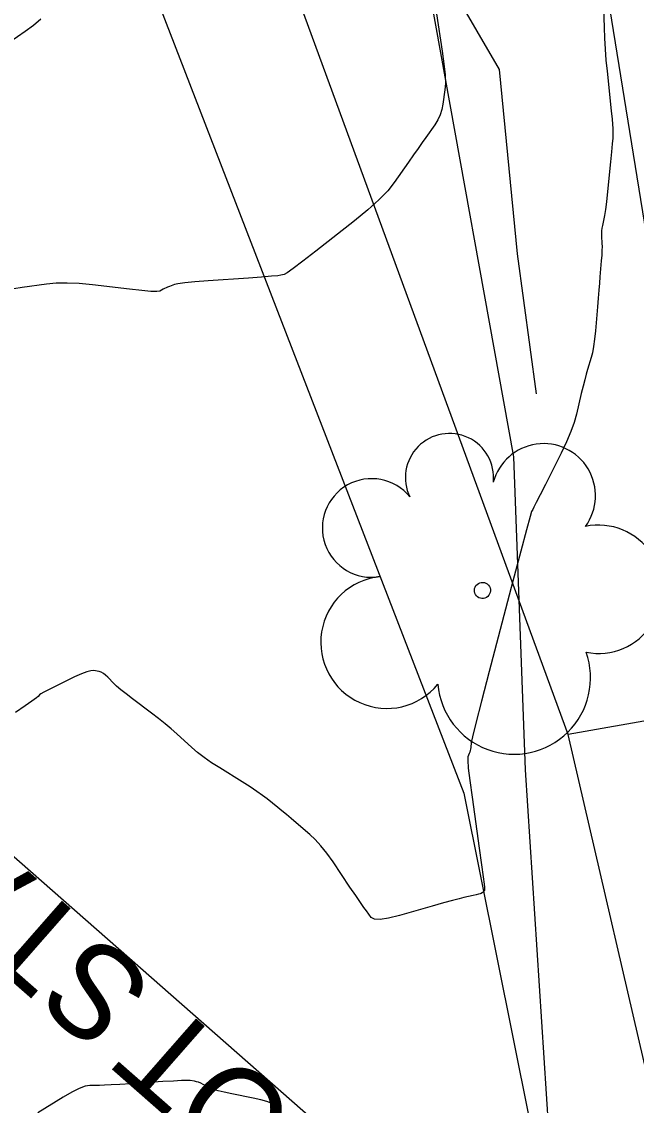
# Model space of a CAD drawing. Extents: x 2030588 to 2035216, y 462285 to 465007.
# Drawn here: x 2031209.6 to 2031227.95, y 464240.7 to 464273.04 of the extents above; entities that cross this region are included whole.
import ezdxf

# ---------------------------------------------------------------- set-up
doc = ezdxf.new("R2010")
doc.units = 0
for name, color, linetype in [('DT_P_Slope_Break_Line', 7, 'Continuous'), ('DT_X_Contour_Major', 7, 'Continuous'), ('DT_X_Contour_Minor', 7, 'Continuous'), ('GE_P_Alignment_100_Cardinal_Points', 7, 'Continuous'), ('MD_P_CONST_LIMITS', 7, 'Continuous'), ('RW_X_Esmt_SH', 7, 'Continuous'), ('SV_X_Toe_of_Slope', 7, 'Continuous'), ('VG_X_Cells', 7, 'Continuous'), ('VG_X_Tree_Line_Lt', 7, 'Continuous')]:
    doc.layers.add(name, color=color, linetype=linetype)

msp = doc.modelspace()

# ---------------------------------------------------------------- linework, layer by layer
at = {"layer": 'DT_P_Slope_Break_Line'}
for p, q in [((2031225.918, 464251.764), (2031216.941, 464276.229)), ((2031234.605, 464253.315), (2031225.918, 464251.764)), ((2031231.768, 464226.532), (2031225.918, 464251.764))]:
    msp.add_line(p, q, dxfattribs=at)
at = {"layer": 'DT_X_Contour_Major'}
msp.add_lwpolyline([(2031226.961, 464273.725), (2031226.988, 464272.871), (2031227.001, 464272.55), (2031227.021, 464272.225), (2031227.047, 464271.897), (2031227.08, 464271.565), (2031227.174, 464270.676), (2031227.206, 464270.375), (2031227.228, 464270.14), (2031227.243, 464269.969), (2031227.248, 464269.864), (2031227.251, 464269.669), (2031227.248, 464269.564), (2031227.236, 464269.394), (2031227.215, 464269.158), (2031227.184, 464268.857), (2031227.091, 464267.968), (2031227.059, 464267.667), (2031227.03, 464267.431), (2031227.006, 464267.259), (2031226.986, 464267.153), (2031226.939, 464266.954), (2031226.925, 464266.879), (2031226.915, 464266.802), (2031226.912, 464266.723), (2031226.914, 464266.642), (2031226.926, 464266.423), (2031226.928, 464266.329), (2031226.926, 464266.211), (2031226.918, 464266.069), (2031226.905, 464265.903), (2031226.865, 464265.428), (2031226.849, 464265.238), (2031226.832, 464265.026), (2031226.812, 464264.791), (2031226.79, 464264.533), (2031226.729, 464263.815), (2031226.705, 464263.563), (2031226.675, 464263.345), (2031226.642, 464263.162), (2031226.604, 464263.014), (2031226.498, 464262.664), (2031226.456, 464262.52), (2031226.411, 464262.352), (2031226.363, 464262.158), (2031226.31, 464261.94), (2031226.167, 464261.326), (2031226.097, 464261.081), (2031225.998, 464260.805), (2031225.867, 464260.5), (2031225.706, 464260.165), (2031225.237, 464259.232), (2031225.081, 464258.922), (2031224.966, 464258.694), (2031224.892, 464258.548), (2031224.858, 464258.483), (2031224.824, 464258.418), (2031224.779, 464258.27), (2031224.672, 464257.876), (2031224.502, 464257.234), (2031224.269, 464256.347), (2031223.563, 464253.65), (2031223.33, 464252.759), (2031223.163, 464252.107), (2031223.06, 464251.695), (2031223.022, 464251.523), (2031223.008, 464251.383), (2031223.001, 464251.333), (2031222.991, 464251.286), (2031222.979, 464251.243), (2031222.964, 464251.203), (2031222.921, 464251.103), (2031222.917, 464250.999), (2031222.936, 464250.763), (2031222.979, 464250.394), (2031223.046, 464249.893), (2031223.256, 464248.379), (2031223.325, 464247.88), (2031223.375, 464247.519), (2031223.406, 464247.296), (2031223.417, 464247.21), (2031223.422, 464247.166), (2031223.423, 464247.15), (2031223.422, 464247.136), (2031223.42, 464247.124), (2031223.416, 464247.114), (2031223.403, 464247.091), (2031223.397, 464247.082), (2031223.388, 464247.072), (2031223.376, 464247.063), (2031223.362, 464247.053), (2031223.318, 464247.025), (2031223.291, 464247.014), (2031223.242, 464246.999), (2031223.17, 464246.981), (2031223.077, 464246.959), (2031222.799, 464246.899), (2031222.662, 464246.866), (2031222.459, 464246.813), (2031222.191, 464246.739), (2031221.857, 464246.646), (2031220.88, 464246.369), (2031220.553, 464246.288), (2031220.303, 464246.25), (2031220.131, 464246.257), (2031220.038, 464246.308), (2031219.892, 464246.504), (2031219.82, 464246.603), (2031219.715, 464246.754), (2031219.575, 464246.957), (2031219.402, 464247.212), (2031218.895, 464247.962), (2031218.709, 464248.224), (2031218.533, 464248.448), (2031218.365, 464248.635), (2031218.206, 464248.784), (2031217.794, 464249.131), (2031217.644, 464249.257), (2031217.503, 464249.375), (2031217.371, 464249.485), (2031217.247, 464249.586), (2031216.928, 464249.846), (2031216.792, 464249.95), (2031216.623, 464250.07), (2031216.42, 464250.204), (2031216.184, 464250.353), (2031215.511, 464250.769), (2031215.269, 464250.925), (2031215.049, 464251.079), (2031214.851, 464251.231), (2031214.675, 464251.382), (2031214.234, 464251.782), (2031214.063, 464251.933), (2031213.88, 464252.087), (2031213.684, 464252.243), (2031213.477, 464252.402), (2031212.909, 464252.828), (2031212.714, 464252.977), (2031212.556, 464253.104), (2031212.434, 464253.208), (2031212.348, 464253.29), (2031212.169, 464253.479), (2031212.102, 464253.542), (2031212.036, 464253.591), (2031211.972, 464253.624), (2031211.909, 464253.643), (2031211.743, 464253.674), (2031211.661, 464253.671), (2031211.539, 464253.638), (2031211.379, 464253.576), (2031211.179, 464253.484), (2031210.594, 464253.2), (2031210.4, 464253.104), (2031210.258, 464253.031), (2031210.167, 464252.979), (2031210.127, 464252.95), (2031210.089, 464252.902), (2031210.036, 464252.859), (2031209.905, 464252.765), (2031209.697, 464252.62), (2031209.412, 464252.425)], dxfattribs=at)
at = {"layer": 'DT_X_Contour_Minor'}
for points in [[(2031210.168, 464273.117), (2031209.946, 464272.926), (2031209.701, 464272.744), (2031209.018, 464272.269)], [(2031221.984, 464273.272), (2031222.155, 464272.162), (2031222.209, 464271.778), (2031222.24, 464271.457), (2031222.25, 464271.2), (2031222.239, 464271.006), (2031222.179, 464270.575), (2031222.147, 464270.415), (2031222.095, 464270.261), (2031222.025, 464270.111), (2031221.935, 464269.966), (2031221.669, 464269.587), (2031221.562, 464269.434), (2031221.44, 464269.26), (2031221.303, 464269.064), (2031221.15, 464268.846), (2031220.724, 464268.237), (2031220.529, 464267.995), (2031220.266, 464267.724), (2031219.935, 464267.426), (2031219.536, 464267.1), (2031218.378, 464266.193), (2031217.994, 464265.895), (2031217.709, 464265.679), (2031217.523, 464265.546), (2031217.437, 464265.495), (2031217.339, 464265.471), (2031217.251, 464265.459), (2031217.059, 464265.441), (2031216.764, 464265.418), (2031216.367, 464265.389), (2031215.168, 464265.304), (2031214.768, 464265.274), (2031214.466, 464265.246), (2031214.263, 464265.221), (2031214.158, 464265.198), (2031214.01, 464265.141), (2031213.957, 464265.12), (2031213.908, 464265.098), (2031213.863, 464265.077), (2031213.823, 464265.055), (2031213.721, 464264.998), (2031213.636, 464264.986), (2031213.457, 464264.991), (2031213.183, 464265.014), (2031212.815, 464265.054), (2031211.709, 464265.186), (2031211.312, 464265.225), (2031210.951, 464265.241), (2031210.625, 464265.236), (2031210.335, 464265.209), (2031209.61, 464265.106), (2031209.359, 464265.065)], [(2031217.187, 464240.699), (2031217.073, 464240.755), (2031216.922, 464240.809), (2031216.735, 464240.861), (2031216.512, 464240.91), (2031215.869, 464241.039), (2031215.648, 464241.087), (2031215.468, 464241.132), (2031215.329, 464241.175), (2031215.23, 464241.216), (2031215.02, 464241.322), (2031214.945, 464241.358), (2031214.877, 464241.386), (2031214.816, 464241.405), (2031214.761, 464241.417), (2031214.626, 464241.437), (2031214.537, 464241.441), (2031214.371, 464241.437), (2031214.129, 464241.425), (2031213.811, 464241.406), (2031212.859, 464241.343), (2031212.533, 464241.322), (2031212.269, 464241.308), (2031212.066, 464241.298), (2031211.924, 464241.295), (2031211.628, 464241.293), (2031211.495, 464241.271), (2031211.319, 464241.205), (2031211.1, 464241.095), (2031210.838, 464240.942), (2031210.082, 464240.475)]]:
    msp.add_lwpolyline(points, dxfattribs=at)
at = {"layer": 'GE_P_Alignment_100_Cardinal_Points'}
msp.add_line((2031185.644, 464268.94), (2031219.463, 464239.26), dxfattribs=at)
at = {"layer": 'MD_P_CONST_LIMITS'}
msp.add_lwpolyline([(2031213.423, 464452.904), (2031204.569, 464426.156), (2031208.548, 464401.477), (2031212.527, 464376.798), (2031213.545, 464351.642), (2031212.78, 464331.262), (2031212.588, 464326.168), (2031200.6, 464313.585), (2031192.908, 464308.049), (2031189.455, 464298.429), (2031209.379, 464281.464), (2031213.118, 464275.067), (2031222.806, 464250.019), (2031227.688, 464225.695), (2031242.004, 464202.354), (2031261.7, 464180.872), (2031268.395, 464156.387), (2031275.973, 464131.824), (2031285.052, 464107.55), (2031291.211, 464093.27), (2031304.871, 464099.462)], dxfattribs=at)
at = {"layer": 'RW_X_Esmt_SH'}
msp.add_line((2031234.838, 464225.767), (2031163.098, 464671.689), dxfattribs=at)
at = {"layer": 'SV_X_Toe_of_Slope'}
msp.add_lwpolyline([(2031217.573, 464288.817), (2031217.191, 464287.542), (2031217.301, 464284.843), (2031218.453, 464281.836), (2031219.883, 464277.797), (2031221.927, 464274.939), (2031223.853, 464271.61), (2031224.394, 464266.111), (2031224.961, 464261.937)], dxfattribs=at)
at = {"layer": 'VG_X_Cells'}
for centre, major_axis, start_param, end_param in [((2031222.373, 464259.434), (0.879, -0.981), 0.735563, 4.435127), ((2031225.182, 464258.895), (1.036, -1.156), 0.208857, 3.720593), ((2031220.047, 464257.93), (-0.982, 1.095), 4.663165, 8.86031), ((2031226.816, 464256.102), (1.278, -1.426), 5.362863, 8.893913), ((2031220.503, 464254.518), (-1.317, 1.469), 5.66, 9.576546), ((2031224.303, 464253.462), (1.524, -1.701), 4.068176, 7.463009)]:
    msp.add_ellipse(centre, major_axis=major_axis, ratio=0.999987, start_param=start_param, end_param=end_param, dxfattribs=at)
msp.add_ellipse((2031223.356, 464256.066), major_axis=(-0.16, 0.179), ratio=0.999987, dxfattribs=at)
at = {"layer": 'VG_X_Tree_Line_Lt'}
msp.add_lwpolyline([(2031171.252, 464603.925), (2031180.58, 464539.236), (2031190.567, 464478.707), (2031195.183, 464442.795), (2031200.666, 464404.618), (2031207.96, 464347.776), (2031213.537, 464319.454), (2031224.286, 464260.057), (2031224.633, 464250.708), (2031227.583, 464205.148)], dxfattribs=at)

# ---------------------------------------------------------------- texts
at = {"layer": 'GE_P_Alignment_100_Cardinal_Points'}
for s, p in [(' STA. ', (2031214.447, 464243.606)), ('POT', (2031219.859, 464238.856))]:
    msp.add_text(s, height=2.7997, rotation=138.729, dxfattribs=at).set_placement(p)

doc.saveas('drawing.dxf')
